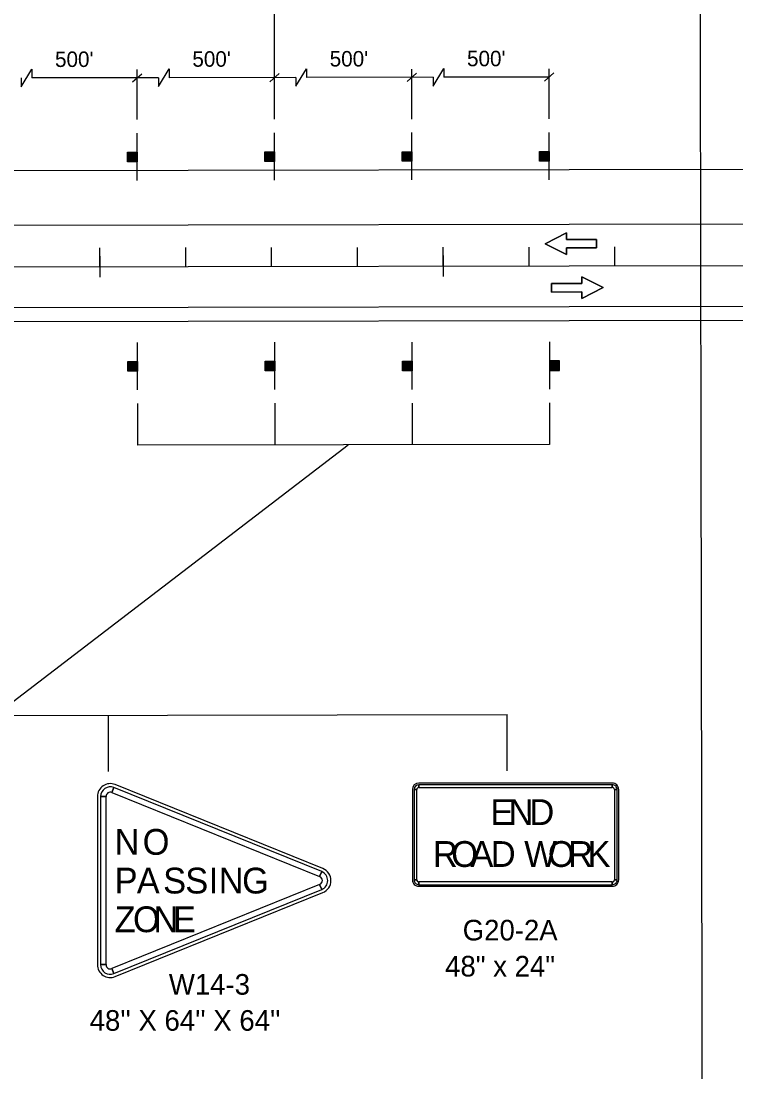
# Model space of a CAD drawing. Extents: x 16513048 to 16518780, y 7009856 to 7010869.
# Drawn here: x 16516417.8 to 16516626, y 7010124.3 to 7010430.3 of the extents above; entities that cross this region are included whole.
import ezdxf

# ---------------------------------------------------------------- set-up
doc = ezdxf.new("R2010")
doc.units = 0
for name, color, linetype in [('dsnNonPlotable', 7, 'Continuous'), ('dsnStdLabel', 7, 'Continuous'), ('Level 2', 7, 'Continuous'), ('Level 5', 7, 'Continuous'), ('NamedBoundary', 7, 'Continuous'), ('SheetBorder', 7, 'Continuous'), ('tdCoTitleBlock', 7, 'Continuous')]:
    doc.layers.add(name, color=color, linetype=linetype)

msp = doc.modelspace()

# ---------------------------------------------------------------- linework, layer by layer
at = {"layer": 'dsnNonPlotable'}
msp.add_line((16513050.27, 7010352.91), (16516699.62, 7010359.27), dxfattribs=at)
for points in [[(16513050.22, 7010380.91), (16516699.59, 7010387.27), (16518770.65, 7010388.94)], [(16518770.66, 7010372.94), (16516699.61, 7010371.27), (16513050.25, 7010364.91)], [(16518770.68, 7010348.94), (16516699.64, 7010347.27), (16513050.29, 7010340.91)], [(16518770.69, 7010344.94), (16516699.64, 7010343.27), (16513050.3, 7010336.91)]]:
    msp.add_lwpolyline(points, dxfattribs=at)
at = {"layer": 'dsnStdLabel'}
for p, q in [((16516505.72, 7010183.52), (16516445.22, 7010207.99)), ((16516590.01, 7010208.43), (16516533.68, 7010208.43)), ((16516533.68, 7010207.18), (16516533.68, 7010207.96)), ((16516590.01, 7010207.96), (16516590.01, 7010207.18)), ((16516444.28, 7010205.67), (16516444.87, 7010207.12)), ((16516531.8, 7010206.55), (16516531.8, 7010180.26)), ((16516532.27, 7010206.55), (16516533.06, 7010206.55)), ((16516590.64, 7010206.55), (16516591.42, 7010206.55)), ((16516591.89, 7010180.26), (16516591.89, 7010206.55)), ((16516440.05, 7010204.51), (16516440.05, 7010155.56)), ((16516440.99, 7010204.51), (16516442.56, 7010204.51)), ((16516505.37, 7010182.65), (16516504.78, 7010181.2)), ((16516533.06, 7010180.26), (16516532.27, 7010180.26)), ((16516591.42, 7010180.26), (16516590.64, 7010180.26)), ((16516504.78, 7010178.88), (16516505.37, 7010177.43)), ((16516533.68, 7010178.85), (16516533.68, 7010179.64)), ((16516533.68, 7010178.38), (16516590.01, 7010178.38)), ((16516590.01, 7010179.64), (16516590.01, 7010178.85)), ((16516445.22, 7010152.08), (16516505.72, 7010176.56)), ((16516442.56, 7010155.56), (16516440.99, 7010155.56)), ((16516444.87, 7010152.95), (16516444.28, 7010154.4))]:
    msp.add_line(p, q, dxfattribs=at)
for points in [[(16516590.01, 7010207.96), (16516533.68, 7010207.96), (16516533.68, 7010207.18), (16516590.01, 7010207.18), (16516590.01, 7010207.96)], [(16516505.37, 7010182.65), (16516444.87, 7010207.12), (16516444.28, 7010205.67), (16516504.78, 7010181.2), (16516505.37, 7010182.65)], [(16516532.27, 7010206.55), (16516532.27, 7010180.26), (16516533.06, 7010180.26), (16516533.06, 7010206.55), (16516532.27, 7010206.55)], [(16516591.42, 7010180.26), (16516591.42, 7010206.55), (16516590.64, 7010206.55), (16516590.64, 7010180.26), (16516591.42, 7010180.26)], [(16516440.99, 7010204.51), (16516440.99, 7010155.56), (16516442.56, 7010155.56), (16516442.56, 7010204.51), (16516440.99, 7010204.51)], [(16516444.87, 7010152.95), (16516505.37, 7010177.43), (16516504.78, 7010178.88), (16516444.28, 7010154.4), (16516444.87, 7010152.95)], [(16516533.68, 7010178.85), (16516590.01, 7010178.85), (16516590.01, 7010179.64), (16516533.68, 7010179.64), (16516533.68, 7010178.85)]]:
    msp.add_lwpolyline(points, close=True, dxfattribs=at)
for centre, radius, start, end in [((16516443.81, 7010204.51), 3.76, 67.9757, 179.9998), ((16516533.68, 7010206.55), 1.88, 90.0002, 179.9998), ((16516533.68, 7010206.55), 1.41, 90.0002, 179.9998), ((16516590.01, 7010206.55), 1.88, 0, 90.0002), ((16516590.01, 7010206.55), 1.41, 0, 90.0002), ((16516443.81, 7010204.51), 2.82, 67.9757, 179.9998), ((16516443.81, 7010204.51), 1.25, 67.9757, 179.9998), ((16516533.68, 7010206.55), 0.626, 90.0002, 179.9998), ((16516590.01, 7010206.55), 0.626, 0, 90.0002), ((16516504.31, 7010180.04), 3.76, 292.0246, 67.976), ((16516504.31, 7010180.04), 1.25, 292.0246, 67.9754), ((16516504.31, 7010180.04), 2.82, 292.0246, 67.9754), ((16516533.68, 7010180.26), 1.88, 179.9998, 270.0001), ((16516533.68, 7010180.26), 1.41, 179.9998, 270.0001), ((16516533.68, 7010180.26), 0.626, 179.9998, 270.0001), ((16516590.01, 7010180.26), 1.88, 270.0001, 0.0003), ((16516590.01, 7010180.26), 1.41, 270.0001, 0.0003), ((16516590.01, 7010180.26), 0.626, 270.0001, 0.0003), ((16516443.81, 7010155.56), 3.76, 179.9998, 292.0246), ((16516443.81, 7010155.56), 2.82, 179.9998, 292.0246), ((16516443.81, 7010155.56), 1.25, 179.9998, 292.0246)]:
    msp.add_arc(centre, radius, start, end, dxfattribs=at)
at = {"layer": 'Level 2'}
for p, q in [((16516491.62, 7010416.26), (16516491.48, 7010498.36)), ((16516451.65, 7010401.64), (16516451.62, 7010416.19)), ((16516491.65, 7010401.71), (16516491.62, 7010416.26)), ((16516531.65, 7010401.78), (16516531.62, 7010416.33)), ((16516571.65, 7010401.85), (16516571.62, 7010416.4)), ((16516457.8, 7010413.79), (16516420.95, 7010413.73)), ((16516450.26, 7010412.58), (16516453, 7010414.98)), ((16516497.8, 7010413.86), (16516460.95, 7010413.8)), ((16516490.25, 7010412.65), (16516493, 7010415.05)), ((16516537.8, 7010413.93), (16516500.95, 7010413.87)), ((16516530.25, 7010412.72), (16516533, 7010415.12)), ((16516571.63, 7010413.99), (16516540.95, 7010413.94)), ((16516570.25, 7010412.79), (16516573, 7010415.19)), ((16516451.65, 7010383.9), (16516451.65, 7010397.67)), ((16516491.65, 7010383.97), (16516491.65, 7010397.74)), ((16516531.65, 7010384.04), (16516531.65, 7010397.81)), ((16516571.65, 7010384.11), (16516571.65, 7010397.88)), ((16516448.99, 7010389.34), (16516448.99, 7010392.13)), ((16516449.15, 7010392.13), (16516449.15, 7010389.34)), ((16516449.26, 7010389.34), (16516449.26, 7010392.13)), ((16516449.42, 7010392.13), (16516449.42, 7010389.34)), ((16516449.53, 7010389.34), (16516449.52, 7010392.13)), ((16516449.74, 7010392.13), (16516449.75, 7010389.34)), ((16516449.85, 7010389.34), (16516449.85, 7010392.13)), ((16516450.07, 7010392.13), (16516450.07, 7010389.34)), ((16516450.25, 7010389.34), (16516450.25, 7010392.13)), ((16516450.41, 7010392.13), (16516450.42, 7010389.34)), ((16516450.53, 7010389.34), (16516450.53, 7010392.13)), ((16516450.66, 7010392.13), (16516450.66, 7010389.34)), ((16516450.83, 7010389.34), (16516450.83, 7010392.13)), ((16516450.93, 7010392.13), (16516450.93, 7010389.34)), ((16516451.04, 7010389.34), (16516451.04, 7010392.13)), ((16516451.17, 7010392.13), (16516451.17, 7010389.34)), ((16516451.31, 7010389.34), (16516451.31, 7010392.13)), ((16516451.45, 7010392.13), (16516451.45, 7010389.34)), ((16516488.99, 7010389.41), (16516488.99, 7010392.2)), ((16516489.15, 7010392.2), (16516489.15, 7010389.41)), ((16516489.26, 7010389.41), (16516489.26, 7010392.2)), ((16516489.42, 7010392.2), (16516489.42, 7010389.41)), ((16516489.53, 7010389.41), (16516489.52, 7010392.2)), ((16516489.74, 7010392.2), (16516489.75, 7010389.41)), ((16516489.85, 7010389.41), (16516489.85, 7010392.2)), ((16516490.07, 7010392.2), (16516490.07, 7010389.41)), ((16516490.25, 7010389.41), (16516490.25, 7010392.2)), ((16516490.41, 7010392.2), (16516490.42, 7010389.41)), ((16516490.53, 7010389.41), (16516490.53, 7010392.2)), ((16516490.66, 7010392.2), (16516490.66, 7010389.41)), ((16516490.83, 7010389.41), (16516490.83, 7010392.2)), ((16516490.93, 7010392.2), (16516490.93, 7010389.41)), ((16516491.04, 7010389.41), (16516491.04, 7010392.2)), ((16516491.17, 7010392.2), (16516491.17, 7010389.41)), ((16516491.31, 7010389.41), (16516491.31, 7010392.2)), ((16516491.45, 7010392.2), (16516491.45, 7010389.41)), ((16516528.99, 7010389.48), (16516528.99, 7010392.27)), ((16516529.15, 7010392.27), (16516529.15, 7010389.48)), ((16516529.26, 7010389.48), (16516529.26, 7010392.27)), ((16516529.42, 7010392.27), (16516529.42, 7010389.48)), ((16516529.53, 7010389.48), (16516529.52, 7010392.27)), ((16516529.74, 7010392.27), (16516529.75, 7010389.48)), ((16516529.85, 7010389.48), (16516529.85, 7010392.27)), ((16516530.07, 7010392.27), (16516530.07, 7010389.48)), ((16516530.25, 7010389.48), (16516530.25, 7010392.27)), ((16516530.41, 7010392.27), (16516530.42, 7010389.48)), ((16516530.53, 7010389.48), (16516530.53, 7010392.27)), ((16516530.66, 7010392.27), (16516530.66, 7010389.48)), ((16516530.83, 7010389.48), (16516530.83, 7010392.27)), ((16516530.93, 7010392.27), (16516530.93, 7010389.48)), ((16516531.04, 7010389.48), (16516531.04, 7010392.27)), ((16516531.17, 7010392.27), (16516531.17, 7010389.48)), ((16516531.31, 7010389.48), (16516531.31, 7010392.27)), ((16516531.45, 7010392.27), (16516531.45, 7010389.48)), ((16516568.99, 7010389.55), (16516568.99, 7010392.34)), ((16516569.15, 7010392.34), (16516569.15, 7010389.55)), ((16516569.26, 7010389.55), (16516569.26, 7010392.34)), ((16516569.42, 7010392.34), (16516569.42, 7010389.55)), ((16516569.53, 7010389.55), (16516569.52, 7010392.34)), ((16516569.74, 7010392.34), (16516569.75, 7010389.55)), ((16516569.85, 7010389.55), (16516569.85, 7010392.34)), ((16516570.07, 7010392.34), (16516570.07, 7010389.55)), ((16516570.25, 7010389.55), (16516570.25, 7010392.34)), ((16516570.41, 7010392.34), (16516570.42, 7010389.55)), ((16516570.53, 7010389.55), (16516570.53, 7010392.34)), ((16516570.66, 7010392.34), (16516570.66, 7010389.55)), ((16516570.83, 7010389.55), (16516570.83, 7010392.34)), ((16516570.93, 7010392.34), (16516570.93, 7010389.55)), ((16516571.04, 7010389.55), (16516571.04, 7010392.34)), ((16516571.17, 7010392.34), (16516571.17, 7010389.55)), ((16516571.31, 7010389.55), (16516571.31, 7010392.34)), ((16516571.45, 7010392.34), (16516571.45, 7010389.55)), ((16516451.74, 7010322.92), (16516451.74, 7010336.69)), ((16516491.74, 7010322.99), (16516491.74, 7010336.76)), ((16516531.74, 7010323.06), (16516531.74, 7010336.83)), ((16516571.83, 7010323.13), (16516571.78, 7010336.9)), ((16516449.07, 7010328.36), (16516449.07, 7010331.16)), ((16516449.23, 7010331.16), (16516449.23, 7010328.36)), ((16516449.34, 7010328.36), (16516449.34, 7010331.16)), ((16516449.5, 7010331.16), (16516449.5, 7010328.36)), ((16516449.61, 7010328.36), (16516449.6, 7010331.16)), ((16516449.82, 7010331.16), (16516449.83, 7010328.36)), ((16516449.93, 7010328.36), (16516449.93, 7010331.16)), ((16516450.15, 7010331.16), (16516450.15, 7010328.36)), ((16516450.34, 7010328.36), (16516450.34, 7010331.16)), ((16516450.5, 7010331.16), (16516450.51, 7010328.36)), ((16516450.61, 7010328.36), (16516450.61, 7010331.16)), ((16516450.74, 7010331.16), (16516450.74, 7010328.36)), ((16516450.91, 7010328.36), (16516450.91, 7010331.16)), ((16516451.01, 7010331.16), (16516451.01, 7010328.36)), ((16516451.12, 7010328.36), (16516451.12, 7010331.16)), ((16516451.26, 7010331.16), (16516451.26, 7010328.36)), ((16516451.39, 7010328.36), (16516451.39, 7010331.16)), ((16516451.53, 7010331.16), (16516451.53, 7010328.36)), ((16516489.07, 7010328.43), (16516489.07, 7010331.23)), ((16516489.23, 7010331.23), (16516489.23, 7010328.43)), ((16516489.34, 7010328.43), (16516489.34, 7010331.23)), ((16516489.5, 7010331.23), (16516489.5, 7010328.43)), ((16516489.61, 7010328.43), (16516489.6, 7010331.23)), ((16516489.82, 7010331.23), (16516489.83, 7010328.43)), ((16516489.93, 7010328.43), (16516489.93, 7010331.23)), ((16516490.15, 7010331.23), (16516490.15, 7010328.43)), ((16516490.34, 7010328.43), (16516490.34, 7010331.23)), ((16516490.5, 7010331.23), (16516490.51, 7010328.43)), ((16516490.61, 7010328.43), (16516490.61, 7010331.23)), ((16516490.74, 7010331.23), (16516490.74, 7010328.43)), ((16516490.91, 7010328.43), (16516490.91, 7010331.23)), ((16516491.01, 7010331.23), (16516491.01, 7010328.43)), ((16516491.12, 7010328.43), (16516491.12, 7010331.23)), ((16516491.26, 7010331.23), (16516491.26, 7010328.43)), ((16516491.39, 7010328.43), (16516491.39, 7010331.23)), ((16516491.53, 7010331.23), (16516491.53, 7010328.43)), ((16516529.07, 7010328.5), (16516529.07, 7010331.3)), ((16516529.23, 7010331.3), (16516529.23, 7010328.5)), ((16516529.34, 7010328.5), (16516529.34, 7010331.3)), ((16516529.5, 7010331.3), (16516529.5, 7010328.5)), ((16516529.61, 7010328.5), (16516529.6, 7010331.3)), ((16516529.82, 7010331.3), (16516529.83, 7010328.5)), ((16516529.93, 7010328.5), (16516529.93, 7010331.3)), ((16516530.15, 7010331.3), (16516530.15, 7010328.5)), ((16516530.34, 7010328.5), (16516530.34, 7010331.3)), ((16516530.5, 7010331.3), (16516530.51, 7010328.5)), ((16516530.61, 7010328.5), (16516530.61, 7010331.3)), ((16516530.74, 7010331.3), (16516530.74, 7010328.5)), ((16516530.91, 7010328.5), (16516530.91, 7010331.3)), ((16516531.01, 7010331.3), (16516531.01, 7010328.5)), ((16516531.12, 7010328.5), (16516531.12, 7010331.3)), ((16516531.26, 7010331.3), (16516531.26, 7010328.5)), ((16516531.39, 7010328.5), (16516531.39, 7010331.3)), ((16516531.53, 7010331.3), (16516531.53, 7010328.5)), ((16516572.01, 7010331.37), (16516572.02, 7010328.57)), ((16516572.16, 7010328.57), (16516572.15, 7010331.37)), ((16516572.28, 7010331.37), (16516572.29, 7010328.57)), ((16516572.42, 7010328.57), (16516572.41, 7010331.37)), ((16516572.52, 7010331.37), (16516572.53, 7010328.57)), ((16516572.64, 7010328.57), (16516572.63, 7010331.37)), ((16516572.8, 7010331.37), (16516572.81, 7010328.57)), ((16516572.94, 7010328.57), (16516572.93, 7010331.37)), ((16516573.04, 7010331.37), (16516573.04, 7010328.57)), ((16516573.21, 7010328.57), (16516573.2, 7010331.37)), ((16516573.39, 7010331.37), (16516573.4, 7010328.58)), ((16516573.61, 7010328.58), (16516573.6, 7010331.37)), ((16516573.72, 7010331.37), (16516573.72, 7010328.58)), ((16516573.93, 7010328.58), (16516573.93, 7010331.38)), ((16516574.04, 7010331.38), (16516574.05, 7010328.58)), ((16516574.21, 7010328.58), (16516574.2, 7010331.38)), ((16516574.31, 7010331.38), (16516574.32, 7010328.58)), ((16516574.48, 7010328.58), (16516574.47, 7010331.38)), ((16516451.74, 7010318.95), (16516451.76, 7010306.8)), ((16516491.74, 7010319.02), (16516491.76, 7010306.87)), ((16516531.74, 7010319.09), (16516531.76, 7010306.94)), ((16516571.74, 7010319.16), (16516571.76, 7010307.01)), ((16516410.15, 7010228.09), (16516513.12, 7010306.91)), ((16516571.76, 7010307.01), (16516451.76, 7010306.8)), ((16516282.93, 7010227.87), (16516559.35, 7010228.35)), ((16516443.29, 7010211.76), (16516443.26, 7010228.15)), ((16516559.38, 7010211.97), (16516559.35, 7010228.35))]:
    msp.add_line(p, q, dxfattribs=at)
for points in [[(16516417.8, 7010413.72), (16516417.8, 7010411.16), (16516420.94, 7010416.28), (16516420.95, 7010413.73)], [(16516457.8, 7010413.79), (16516457.8, 7010411.23), (16516460.94, 7010416.35), (16516460.95, 7010413.8)], [(16516497.8, 7010413.85), (16516497.8, 7010411.3), (16516500.94, 7010416.42), (16516500.95, 7010413.87)], [(16516537.8, 7010413.92), (16516537.8, 7010411.37), (16516540.94, 7010416.49), (16516540.95, 7010413.94)]]:
    msp.add_lwpolyline(points, dxfattribs=at)
for points in [[(16516451.61, 7010392.13), (16516451.61, 7010389.32), (16516448.79, 7010389.32), (16516448.79, 7010392.13)], [(16516491.61, 7010392.2), (16516491.61, 7010389.39), (16516488.79, 7010389.39), (16516488.79, 7010392.2)], [(16516531.61, 7010392.27), (16516531.61, 7010389.46), (16516528.79, 7010389.46), (16516528.79, 7010392.27)], [(16516571.61, 7010392.34), (16516571.61, 7010389.53), (16516568.79, 7010389.53), (16516568.79, 7010392.34)], [(16516585.43, 7010366.74), (16516585.43, 7010364.24), (16516576.68, 7010364.23), (16516576.69, 7010362.36), (16516570.43, 7010365.47), (16516576.68, 7010368.61), (16516576.68, 7010366.73)], [(16516572.35, 7010351.41), (16516572.34, 7010353.91), (16516581.09, 7010353.92), (16516581.09, 7010355.8), (16516587.34, 7010352.68), (16516581.1, 7010349.55), (16516581.1, 7010351.42)], [(16516451.69, 7010331.16), (16516451.69, 7010328.34), (16516448.87, 7010328.34), (16516448.87, 7010331.16)], [(16516491.69, 7010331.23), (16516491.69, 7010328.41), (16516488.87, 7010328.41), (16516488.87, 7010331.23)], [(16516531.69, 7010331.3), (16516531.69, 7010328.48), (16516528.87, 7010328.48), (16516528.87, 7010331.3)], [(16516571.85, 7010331.37), (16516571.86, 7010328.55), (16516574.68, 7010328.56), (16516574.67, 7010331.38)]]:
    msp.add_lwpolyline(points, close=True, dxfattribs=at)
at = {"layer": 'Level 5'}
for points in [[(16516576.68, 7010366.73), (16516576.68, 7010368.61), (16516570.43, 7010365.47), (16516576.69, 7010362.36), (16516576.68, 7010364.23), (16516585.43, 7010364.24), (16516585.43, 7010366.74), (16516576.68, 7010366.73)], [(16516581.1, 7010351.42), (16516581.1, 7010349.55), (16516587.34, 7010352.68), (16516581.09, 7010355.8), (16516581.09, 7010353.92), (16516572.34, 7010353.91), (16516572.35, 7010351.41), (16516581.1, 7010351.42)]]:
    msp.add_lwpolyline(points, dxfattribs=at)
at = {"layer": 'NamedBoundary'}
msp.add_lwpolyline([(16515047.4, 7010866.4), (16515049.16, 7009856.4), (16516616.66, 7009859.13), (16516614.9, 7010869.13)], close=True, dxfattribs=at)
at = {"layer": 'SheetBorder'}
for p, q in [((16516465.79, 7010358.87), (16516465.78, 7010364.33)), ((16516490.79, 7010358.91), (16516490.78, 7010364.37)), ((16516515.79, 7010358.95), (16516515.78, 7010364.41)), ((16516565.79, 7010359.04), (16516565.78, 7010364.5)), ((16516590.79, 7010359.09), (16516590.78, 7010364.55)), ((16516615.79, 7010359.13), (16516615.78, 7010364.59)), ((16516440.78, 7010361.88), (16516440.79, 7010355.76)), ((16516540.78, 7010362.06), (16516540.79, 7010355.94))]:
    msp.add_line(p, q, dxfattribs=at)
at = {"layer": 'tdCoTitleBlock'}
for p, q in [((16516440.79, 7010358.82), (16516440.78, 7010364.28)), ((16516540.79, 7010359), (16516540.78, 7010364.46))]:
    msp.add_line(p, q, dxfattribs=at)

# ---------------------------------------------------------------- texts
at = {"layer": 'dsnStdLabel'}
for s, height, p in [('E', 7.51, (16516554.5, 7010196.22)), ('N', 7.51, (16516559.82, 7010196.22)), ('D', 7.51, (16516565.87, 7010196.22)), ('N', 7.51, (16516445.05, 7010187.55)), ('O', 7.51, (16516453.23, 7010187.55)), ('R', 7.51, (16516537.74, 7010184.02)), ('O', 7.51, (16516543.09, 7010184.02)), ('A', 7.51, (16516548.68, 7010184.02)), ('D', 7.51, (16516554.62, 7010184.02)), ('W', 7.51, (16516564.36, 7010184.02)), ('O', 7.51, (16516571.23, 7010184.02)), ('R', 7.51, (16516577.13, 7010184.02)), ('K', 7.51, (16516582.78, 7010184.02)), ('P', 7.51, (16516445.05, 7010176.28)), ('A', 7.51, (16516451.5, 7010176.28)), ('S', 7.51, (16516459.19, 7010176.28)), ('S', 7.51, (16516465.64, 7010176.28)), ('I', 7.51, (16516472.45, 7010176.28)), ('N', 7.51, (16516475.38, 7010176.28)), ('G', 7.51, (16516482.19, 7010176.28)), ('Z', 7.51, (16516445.05, 7010165.02)), ('O', 7.51, (16516450.42, 7010165.02)), ('N', 7.51, (16516456.35, 7010165.02)), ('E', 7.51, (16516462.03, 7010165.02)), ('G20-2A', 6, (16516546.44, 7010162.61)), ('48" x 24"', 6, (16516541.32, 7010152.11)), ('W14-3', 6, (16516460.86, 7010146.82)), ("48'' X 64'' X 64''", 6, (16516437.79, 7010136.32))]:
    msp.add_text(s, height=height, dxfattribs=at).set_placement(p)
at = {"layer": 'Level 2'}
for p in [(16516427.7, 7010416.93), (16516467.7, 7010417), (16516507.7, 7010417.07), (16516547.7, 7010417.14)]:
    msp.add_text("500'", height=4.5, dxfattribs=at).set_placement(p)

doc.saveas('drawing.dxf')
